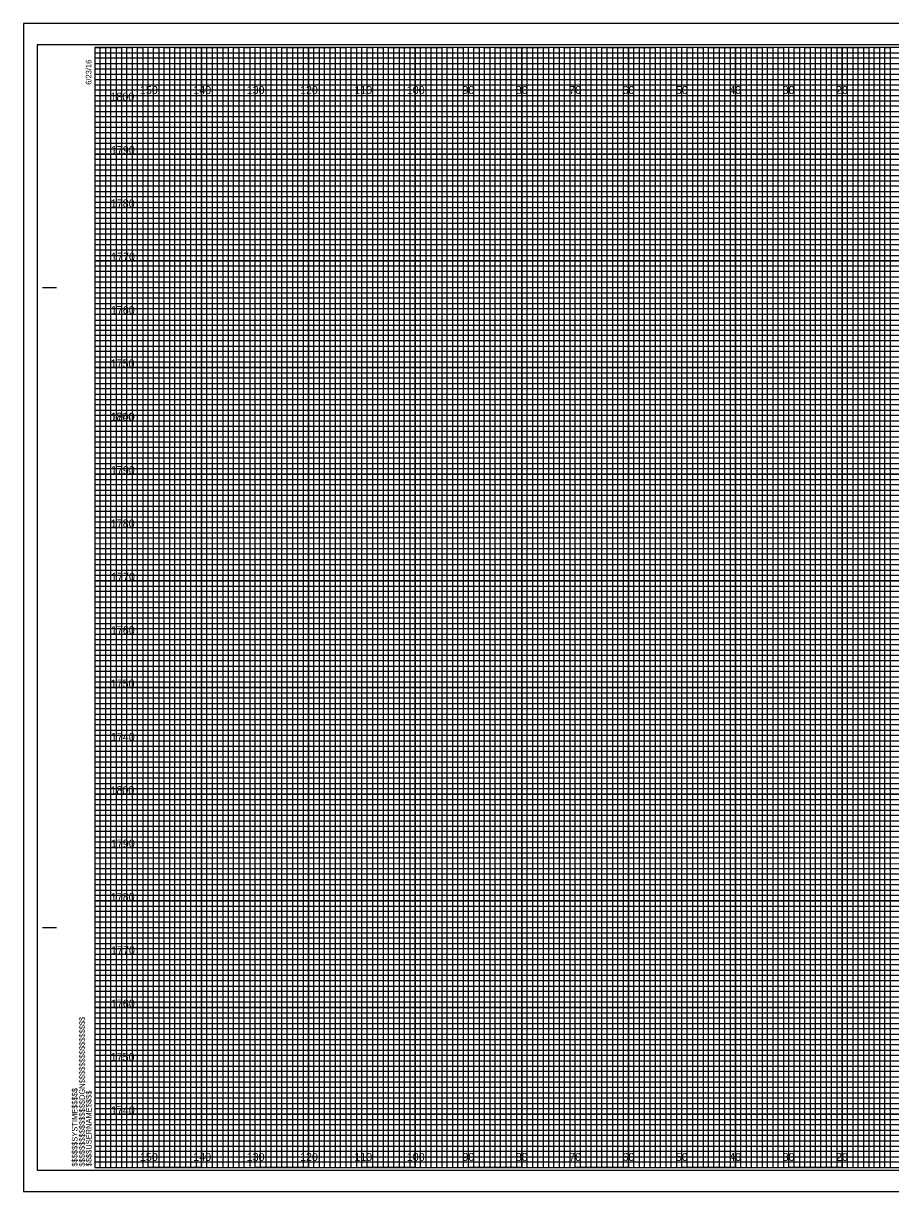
# Model space of a CAD drawing. Extents: x -15 to 323, y -5 to 6170.
# Drawn here: x -13.4 to 149.1, y 1755.5 to 1974.5 of the extents above; entities that cross this region are included whole.
import ezdxf

# ---------------------------------------------------------------- set-up
doc = ezdxf.new("R2010")
doc.units = 0
for name, color, linetype in [('Prop XS DDE', 7, 'Continuous'), ('Prop XS DDE Slope Text', 7, 'Continuous'), ('Prop XS DDE Text', 7, 'Continuous'), ('Prop XS Earthwork Shape', 7, 'Continuous'), ('Prop XS Noise Wall', 7, 'Continuous'), ('Prop XS Retaining Wall', 7, 'Continuous'), ('Prop XS Station Labels', 7, 'Continuous'), ('Scratch_Level_3', 7, 'Continuous'), ('Scratch_Level_7', 7, 'Continuous'), ('Scratch_Level_8', 7, 'Continuous'), ('Sheet Cross Section Grid Minor 1 CELL', 7, 'Continuous')]:
    doc.layers.add(name, color=color, linetype=linetype)

msp = doc.modelspace()

# ---------------------------------------------------------------- linework, layer by layer
at = {"layer": 'Prop XS DDE'}
msp.add_lwpolyline([(-13.4, 1755.5), (323.3, 1755.5), (323.3, 1974.5), (-13.4, 1974.5)], close=True, dxfattribs=at)
at = {"layer": 'Prop XS DDE Slope Text'}
msp.add_lwpolyline([(-10.8, 1759.5), (322.4, 1759.5), (322.4, 1970.5), (-10.8, 1970.5)], close=True, dxfattribs=at)
at = {"layer": 'Prop XS DDE Text'}
for p, q in [((10, 1760), (10, 1970)), ((20, 1760), (20, 1970)), ((30, 1760), (30, 1970)), ((40, 1760), (40, 1970)), ((50, 1760), (50, 1970)), ((60, 1760), (60, 1970)), ((70, 1760), (70, 1970)), ((80, 1760), (80, 1970)), ((90, 1760), (90, 1970)), ((100, 1760), (100, 1970)), ((110, 1760), (110, 1970)), ((120, 1760), (120, 1970)), ((130, 1760), (130, 1970)), ((140, 1760), (140, 1970)), ((0, 1960), (320, 1960)), ((0, 1950), (320, 1950)), ((0, 1940), (320, 1940)), ((0, 1930), (320, 1930)), ((0, 1920), (320, 1920)), ((0, 1910), (320, 1910)), ((0, 1900), (320, 1900)), ((0, 1890), (320, 1890)), ((0, 1880), (320, 1880)), ((0, 1870), (320, 1870)), ((0, 1860), (320, 1860)), ((0, 1850), (320, 1850)), ((0, 1840), (320, 1840)), ((0, 1830), (320, 1830)), ((0, 1820), (320, 1820)), ((0, 1810), (320, 1810)), ((0, 1800), (320, 1800)), ((0, 1790), (320, 1790)), ((0, 1780), (320, 1780)), ((0, 1770), (320, 1770))]:
    msp.add_line(p, q, dxfattribs=at)
at = {"layer": 'Prop XS Earthwork Shape'}
for p, q in [((10, 1970), (0, 1970)), ((10, 1760), (10, 1970)), ((30, 1970), (20, 1970)), ((20, 1970), (20, 1760)), ((30, 1760), (30, 1970)), ((50, 1970), (40, 1970)), ((40, 1970), (40, 1760)), ((50, 1760), (50, 1970)), ((70, 1970), (60, 1970)), ((60, 1970), (60, 1760)), ((70, 1760), (70, 1970)), ((90, 1970), (80, 1970)), ((80, 1970), (80, 1760)), ((90, 1760), (90, 1970)), ((110, 1970), (100, 1970)), ((100, 1970), (100, 1760)), ((110, 1760), (110, 1970)), ((130, 1970), (120, 1970)), ((120, 1970), (120, 1760)), ((130, 1760), (130, 1970)), ((150, 1970), (140, 1970)), ((140, 1970), (140, 1760)), ((20, 1760), (10, 1760)), ((40, 1760), (30, 1760)), ((60, 1760), (50, 1760)), ((80, 1760), (70, 1760)), ((100, 1760), (90, 1760)), ((120, 1760), (110, 1760)), ((140, 1760), (130, 1760))]:
    msp.add_line(p, q, dxfattribs=at)
for points in [[(0, 1960), (320, 1960), (320, 1950), (0, 1950)], [(0, 1940), (320, 1940), (320, 1930), (0, 1930)], [(0, 1920), (320, 1920), (320, 1910), (0, 1910)], [(0, 1900), (320, 1900), (320, 1890), (0, 1890)], [(0, 1880), (320, 1880), (320, 1870), (0, 1870)], [(0, 1860), (320, 1860), (320, 1850), (0, 1850)], [(0, 1840), (320, 1840), (320, 1830), (0, 1830)], [(0, 1820), (320, 1820), (320, 1810), (0, 1810)], [(0, 1800), (320, 1800), (320, 1790), (0, 1790)], [(0, 1780), (320, 1780), (320, 1770), (0, 1770)]]:
    msp.add_lwpolyline(points, dxfattribs=at)
at = {"layer": 'Prop XS Noise Wall'}
for p, q in [((-9.8, 1925), (-7.3, 1925)), ((-9.7, 1925), (-7.2, 1925)), ((-9.8, 1805), (-7.3, 1805)), ((-9.7, 1805), (-7.2, 1805)), ((0, 1760), (0, 1760)), ((0, 1760), (0, 1760)), ((0, 1760), (0, 1760)), ((0, 1760), (0, 1760)), ((0, 1760), (0, 1760)), ((0, 1760), (0, 1760)), ((0, 1760), (0, 1760))]:
    msp.add_line(p, q, dxfattribs=at)
msp.add_lwpolyline([(320, 1970), (0, 1970), (0, 1760), (320, 1760)], close=True, dxfattribs=at)
at = {"layer": 'Prop XS Retaining Wall'}
for points in [[(0, 1760), (1, 1760), (1, 1970), (2, 1970), (2, 1760)], [(2, 1760), (3, 1760), (3, 1970), (4, 1970), (4, 1760)], [(5, 1760), (6, 1760), (6, 1970), (7, 1970), (7, 1760)], [(7, 1760), (8, 1760), (8, 1970), (9, 1970), (9, 1760)], [(10, 1760), (11, 1760), (11, 1970), (12, 1970), (12, 1760)], [(12, 1760), (13, 1760), (13, 1970), (14, 1970), (14, 1760)], [(15, 1760), (16, 1760), (16, 1970), (17, 1970), (17, 1760)], [(17, 1760), (18, 1760), (18, 1970), (19, 1970), (19, 1760)], [(20, 1760), (21, 1760), (21, 1970), (22, 1970), (22, 1760)], [(22, 1760), (23, 1760), (23, 1970), (24, 1970), (24, 1760)], [(25, 1760), (26, 1760), (26, 1970), (27, 1970), (27, 1760)], [(27, 1760), (28, 1760), (28, 1970), (29, 1970), (29, 1760)], [(30, 1760), (31, 1760), (31, 1970), (32, 1970), (32, 1760)], [(32, 1760), (33, 1760), (33, 1970), (34, 1970), (34, 1760)], [(35, 1760), (36, 1760), (36, 1970), (37, 1970), (37, 1760)], [(37, 1760), (38, 1760), (38, 1970), (39, 1970), (39, 1760)], [(40, 1760), (41, 1760), (41, 1970), (42, 1970), (42, 1760)], [(42, 1760), (43, 1760), (43, 1970), (44, 1970), (44, 1760)], [(45, 1760), (46, 1760), (46, 1970), (47, 1970), (47, 1760)], [(47, 1760), (48, 1760), (48, 1970), (49, 1970), (49, 1760)], [(50, 1760), (51, 1760), (51, 1970), (52, 1970), (52, 1760)], [(52, 1760), (53, 1760), (53, 1970), (54, 1970), (54, 1760)], [(55, 1760), (56, 1760), (56, 1970), (57, 1970), (57, 1760)], [(57, 1760), (58, 1760), (58, 1970), (59, 1970), (59, 1760)], [(60, 1760), (61, 1760), (61, 1970), (62, 1970), (62, 1760)], [(62, 1760), (63, 1760), (63, 1970), (64, 1970), (64, 1760)], [(65, 1760), (66, 1760), (66, 1970), (67, 1970), (67, 1760)], [(67, 1760), (68, 1760), (68, 1970), (69, 1970), (69, 1760)], [(70, 1760), (71, 1760), (71, 1970), (72, 1970), (72, 1760)], [(72, 1760), (73, 1760), (73, 1970), (74, 1970), (74, 1760)], [(75, 1760), (76, 1760), (76, 1970), (77, 1970), (77, 1760)], [(77, 1760), (78, 1760), (78, 1970), (79, 1970), (79, 1760)], [(80, 1760), (81, 1760), (81, 1970), (82, 1970), (82, 1760)], [(82, 1760), (83, 1760), (83, 1970), (84, 1970), (84, 1760)], [(85, 1760), (86, 1760), (86, 1970), (87, 1970), (87, 1760)], [(87, 1760), (88, 1760), (88, 1970), (89, 1970), (89, 1760)], [(90, 1760), (91, 1760), (91, 1970), (92, 1970), (92, 1760)], [(92, 1760), (93, 1760), (93, 1970), (94, 1970), (94, 1760)], [(95, 1760), (96, 1760), (96, 1970), (97, 1970), (97, 1760)], [(97, 1760), (98, 1760), (98, 1970), (99, 1970), (99, 1760)], [(100, 1760), (101, 1760), (101, 1970), (102, 1970), (102, 1760)], [(102, 1760), (103, 1760), (103, 1970), (104, 1970), (104, 1760)], [(105, 1760), (106, 1760), (106, 1970), (107, 1970), (107, 1760)], [(107, 1760), (108, 1760), (108, 1970), (109, 1970), (109, 1760)], [(110, 1760), (111, 1760), (111, 1970), (112, 1970), (112, 1760)], [(112, 1760), (113, 1760), (113, 1970), (114, 1970), (114, 1760)], [(115, 1760), (116, 1760), (116, 1970), (117, 1970), (117, 1760)], [(117, 1760), (118, 1760), (118, 1970), (119, 1970), (119, 1760)], [(120, 1760), (121, 1760), (121, 1970), (122, 1970), (122, 1760)], [(122, 1760), (123, 1760), (123, 1970), (124, 1970), (124, 1760)], [(125, 1760), (126, 1760), (126, 1970), (127, 1970), (127, 1760)], [(127, 1760), (128, 1760), (128, 1970), (129, 1970), (129, 1760)], [(130, 1760), (131, 1760), (131, 1970), (132, 1970), (132, 1760)], [(132, 1760), (133, 1760), (133, 1970), (134, 1970), (134, 1760)], [(135, 1760), (136, 1760), (136, 1970), (137, 1970), (137, 1760)], [(137, 1760), (138, 1760), (138, 1970), (139, 1970), (139, 1760)], [(140, 1760), (141, 1760), (141, 1970), (142, 1970), (142, 1760)], [(142, 1760), (143, 1760), (143, 1970), (144, 1970), (144, 1760)], [(145, 1760), (146, 1760), (146, 1970), (147, 1970), (147, 1760)], [(147, 1760), (148, 1760), (148, 1970), (149, 1970), (149, 1760)]]:
    msp.add_lwpolyline(points, dxfattribs=at)
at = {"layer": 'Prop XS Station Labels'}
for points in [[(0, 1970), (5, 1970), (5, 1760), (15, 1760), (15, 1970), (25, 1970), (25, 1760), (35, 1760), (35, 1970), (45, 1970), (45, 1760), (55, 1760), (55, 1970), (65, 1970), (65, 1760), (75, 1760), (75, 1970), (85, 1970), (85, 1760), (95, 1760), (95, 1970), (105, 1970), (105, 1760), (115, 1760), (115, 1970), (125, 1970), (125, 1760), (135, 1760), (135, 1970), (145, 1970), (145, 1760), (155, 1760)], [(0, 1965), (275, 1965)], [(0, 1945), (320, 1945), (320, 1955), (0, 1955)], [(0, 1925), (320, 1925), (320, 1935), (0, 1935)], [(0, 1905), (320, 1905), (320, 1915), (0, 1915)], [(0, 1885), (320, 1885), (320, 1895), (0, 1895)], [(0, 1865), (320, 1865), (320, 1875), (0, 1875)], [(0, 1845), (320, 1845), (320, 1855), (0, 1855)], [(0, 1825), (320, 1825), (320, 1835), (0, 1835)], [(0, 1805), (320, 1805), (320, 1815), (0, 1815)], [(0, 1785), (320, 1785), (320, 1795), (0, 1795)], [(0, 1765), (320, 1765), (320, 1775), (0, 1775)]]:
    msp.add_lwpolyline(points, dxfattribs=at)
at = {"layer": 'Scratch_Level_7'}
for p, q in [((323.3, 1974.5), (-13.4, 1974.5)), ((-13.4, 1974.5), (-13.4, 1755.5)), ((-13.4, 1755.5), (323.3, 1755.5))]:
    msp.add_line(p, q, dxfattribs=at)
at = {"layer": 'Sheet Cross Section Grid Minor 1 CELL'}
for p, q in [((0, 1969), (260, 1969)), ((260, 1967.98), (0, 1967.98)), ((0, 1967.98), (0, 1967)), ((0, 1967), (260, 1967)), ((260, 1965.89), (0, 1965.89)), ((0, 1965.89), (0, 1964)), ((0, 1964), (320, 1964))]:
    msp.add_line(p, q, dxfattribs=at)
for points in [[(0, 1963), (270, 1963), (320, 1963), (320, 1962), (0, 1962)], [(0, 1961), (320, 1961), (320, 1959), (0, 1959)], [(0, 1958), (320, 1958), (320, 1957), (0, 1956.98)], [(0, 1956), (320, 1956), (320, 1954), (0, 1954)], [(0, 1953), (320, 1953), (320, 1952), (0, 1952)], [(0, 1951), (320, 1951), (320, 1949), (0, 1949)], [(0, 1948), (320, 1948), (320, 1947), (0, 1947)], [(0, 1946), (320, 1946), (320, 1944), (0, 1944)], [(0, 1943), (320, 1943), (320, 1942), (0, 1942)], [(0, 1941), (320, 1941), (320, 1939), (0, 1939)], [(0, 1938), (320, 1938), (320, 1937), (0, 1937)], [(0, 1936), (320, 1936), (320, 1933.95), (320, 1933), (320, 1932), (0, 1932)], [(0, 1934), (320, 1934), (320, 1933), (0, 1933)], [(0, 1931), (320, 1931), (320, 1929), (0, 1929.03)], [(0, 1929.03), (320, 1929), (320, 1928), (0, 1928)], [(0, 1927), (320, 1927), (320, 1926), (0, 1926)], [(0, 1924), (320, 1924), (320, 1923), (0, 1923)], [(0, 1922), (320, 1922), (320, 1921), (0, 1921)], [(-0.07, 1918.89), (320, 1918.89), (320, 1917.88), (-0.07, 1917.88)], [(0, 1917), (320, 1917), (320, 1916), (0, 1916)], [(0, 1914), (320, 1914), (320, 1913), (0, 1913)], [(0, 1912), (320, 1912), (320, 1911), (0, 1911)], [(0, 1909), (320, 1909), (320, 1908), (0, 1908)], [(0, 1907), (320, 1907), (320, 1906), (0, 1906)], [(0, 1904), (320, 1904), (320, 1903), (0, 1903)], [(0, 1902), (320, 1902), (320, 1901), (0, 1901)], [(0, 1899), (320, 1899), (319.99, 1897.98), (0, 1898)], [(0, 1897), (320, 1897), (320, 1896), (0, 1896)], [(0, 1894), (320, 1894), (320, 1893), (0, 1893)], [(0, 1892), (320, 1892), (320, 1891), (0, 1891)], [(0, 1889), (320, 1889), (320, 1888), (0, 1888)], [(0, 1887), (320, 1887), (320, 1886), (0, 1886)], [(0, 1884), (320, 1884), (320, 1883), (0, 1883)], [(0, 1882), (320, 1882), (320, 1881), (0, 1881)], [(0, 1879), (320, 1879), (320, 1878), (0, 1878)], [(0, 1876.99), (320.07, 1876.91), (320, 1876), (0, 1876)], [(0, 1874), (320, 1874), (320, 1873), (0, 1873)], [(0, 1872), (320, 1872), (320, 1871), (0, 1871)], [(0, 1869), (320, 1869), (320, 1868), (0, 1868)], [(0, 1867), (320, 1867), (320, 1866), (0, 1866)], [(0, 1864), (320, 1864), (320, 1863), (0, 1863)], [(0, 1862), (320, 1862), (320, 1861), (0, 1861)], [(0, 1859), (320, 1859), (320, 1858), (0, 1858)], [(0, 1857), (320, 1857), (320, 1856), (0, 1856)], [(0, 1854), (320, 1854), (320, 1853), (0, 1853)], [(0, 1852), (320, 1852), (320, 1851), (0, 1851)], [(0, 1849), (320, 1849), (320, 1848), (0, 1848)], [(0, 1847), (320, 1847), (320, 1846), (0, 1846)], [(0, 1844), (320, 1844), (320, 1843), (0, 1843)], [(0, 1842), (320, 1842), (320, 1841), (0, 1841)], [(0, 1839), (320, 1839), (319.99, 1837.98), (0, 1838)], [(0, 1837), (320, 1837), (320, 1836), (0, 1836)], [(0, 1834), (320, 1834), (320, 1833), (0, 1833)], [(0, 1832), (320, 1832), (320, 1831), (0, 1831)], [(0, 1829), (320, 1829), (320, 1828), (0, 1828)], [(0, 1827), (320, 1827), (320, 1826), (0, 1826)], [(0, 1824), (320, 1824), (320, 1823), (0, 1823)], [(0, 1822), (320, 1822), (320, 1821), (0, 1821)], [(0, 1819), (320, 1819), (320, 1818), (0, 1818)], [(0, 1816.99), (320.07, 1816.91), (320, 1816), (0, 1816)], [(0, 1814), (320, 1814), (320, 1813), (0, 1813)], [(0, 1812), (320, 1812), (320, 1811), (0, 1811)], [(0, 1809), (320, 1809), (320, 1808), (0, 1808)], [(0, 1807), (320, 1807), (320, 1806), (0, 1806)], [(0, 1804), (320, 1804), (320, 1803), (0, 1803)], [(0, 1802), (320, 1802), (320, 1801), (0, 1801)], [(0, 1799), (320, 1799), (320, 1798), (0, 1798)], [(0, 1797), (320, 1797), (320, 1796), (0, 1796)], [(0, 1794), (320, 1794), (320, 1793), (0, 1793)], [(0, 1792), (320, 1792), (320, 1791), (0, 1791)], [(0, 1789), (320, 1789), (320, 1788), (0, 1788)], [(0, 1787), (320, 1787), (320, 1786), (0, 1786)], [(0, 1784), (320, 1784), (320, 1783), (0, 1783)], [(0, 1782), (320, 1782), (320, 1781), (0, 1781)], [(0, 1779), (320, 1779), (320, 1778), (0, 1778)], [(0, 1777), (320, 1777), (320, 1776), (0, 1776)], [(0, 1774), (320, 1774), (320, 1773), (0, 1773)], [(0, 1772), (320, 1772), (320, 1771), (0, 1771)], [(0, 1769), (320, 1769), (320, 1768), (0, 1768)], [(0, 1767), (320, 1767), (320, 1766), (0, 1766)], [(0, 1764), (320, 1764), (320, 1763), (0, 1763)], [(0, 1762), (320, 1762), (320, 1761), (0, 1761)]]:
    msp.add_lwpolyline(points, dxfattribs=at)

# ---------------------------------------------------------------- texts
at = {"layer": 'Prop XS Noise Wall'}
for s, p in [('6/23/16', (-0.65, 1963)), ('$$$$$$$$$$$$$$$$DGN$$$$$$$$$$$$$$$$', (-1.88, 1760.18)), ('$$$$$$SYSTIME$$$$$', (-3.26, 1760.18)), ('$$$$USERNAME$$$$', (-0.62, 1760.23))]:
    msp.add_text(s, height=1.05, rotation=90, dxfattribs=at).set_placement(p)
at = {"layer": 'Scratch_Level_3'}
for s, p in [('1800', (2.92, 1960)), ('1790', (3, 1950)), ('1780', (2.98, 1940)), ('1770', (3.04, 1930)), ('1760', (3, 1920)), ('1750', (2.96, 1910)), ('1800', (2.92, 1900)), ('1740', (3, 1900)), ('1790', (3, 1890)), ('1780', (2.98, 1880)), ('1770', (3.04, 1870)), ('1760', (3, 1860)), ('1750', (2.96, 1850)), ('1740', (3, 1840)), ('1800', (2.92, 1830)), ('1790', (3, 1820)), ('1780', (2.98, 1810)), ('1770', (3.04, 1800)), ('1760', (3, 1790)), ('1750', (2.96, 1780)), ('1740', (3, 1770))]:
    msp.add_text(s, height=1.5, dxfattribs=at).set_placement(p)
at = {"layer": 'Scratch_Level_8'}
for s, p in [('150', (8.44, 1961.25)), ('140', (18.44, 1961.25)), ('130', (28.44, 1961.25)), ('120', (38.44, 1961.25)), ('110', (48.62, 1961.25)), ('100', (58.44, 1961.25)), ('90', (68.86, 1961.25)), ('80', (78.86, 1961.25)), ('70', (88.86, 1961.25)), ('60', (98.86, 1961.25)), ('50', (108.86, 1961.25)), ('40', (118.86, 1961.25)), ('30', (128.86, 1961.25)), ('20', (138.86, 1961.25)), ('150', (8.44, 1761.25)), ('140', (18.44, 1761.25)), ('130', (28.44, 1761.25)), ('120', (38.44, 1761.25)), ('110', (48.62, 1761.25)), ('100', (58.44, 1761.25)), ('90', (68.86, 1761.25)), ('80', (78.86, 1761.25)), ('70', (88.86, 1761.25)), ('60', (98.86, 1761.25)), ('50', (108.86, 1761.25)), ('40', (118.86, 1761.25)), ('30', (128.86, 1761.25)), ('20', (138.86, 1761.25))]:
    msp.add_text(s, height=1.5, dxfattribs=at).set_placement(p)

doc.saveas('drawing.dxf')
